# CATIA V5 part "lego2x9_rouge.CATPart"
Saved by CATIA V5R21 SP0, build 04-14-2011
Part number: lego2x9_rouge
Definition: Brique LEGO® 2x9, couleur Rouge
Description: Brique LEGO® 2x9, couleur Rouge
Property "SUPPLIER": "LEGO®"
Property "SUPPLIER": "LEGO®"
Property "DESIGN": "Brique LEGO® 2x9, couleur Rouge"
Property "DESIGN": "Brique LEGO® 2x9, couleur Rouge"
Property "TraceParts.PartNumber": "10-20122010-073060"
Property "TRACEPARTS": "TRACEPARTS"
Property "TraceParts.PartTitle": "Brique LEGO® 2x9"
Property "TraceParts.InstanceId": "10-20122010-07306010UFQ9W313DGN2O2A8ITDW7CR"
Property "TraceParts.PartVersion": "1.0.7"
Property "TraceParts.PartLanguage": "fr"
Bounding box of the stored display mesh (mm): x -4 to 68, y 0 to 11.2, z -4 to 12
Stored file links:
  C:\Users\2027.DESARCY-LEMIE30\Desktop\Legos\traité\lego2x9_rouge.CATPart
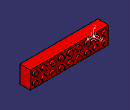
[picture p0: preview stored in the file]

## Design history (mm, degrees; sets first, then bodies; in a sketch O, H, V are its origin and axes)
AxisSystem1: origin (0, 0, 0), X (1, 0, 0), Y (0, 1, 0), Z (0, 0, 1)
Body1 "lego2x9_rouge" (main body)
  Solid1: solid without history
  Sketch1 on face of Solid1, origin (0, 0, 0), H (1, 0, 0), V (0, 0, 1)
    line L1 (-3, 11) -> (67, 11)
    line L2 (67, 11) -> (67, -3)
    line L3 (67, -3) -> (-3, -3)
    line L4 (-3, -3) -> (-3, 11)
    reference projected line E1 (-4, 12) -> (68, 12) from edge [face of Solid1 | face of Solid1]
    reference projected line E2 (-4, -4) -> (-4, 12) from edge [face of Solid1 | face of Solid1]
    reference projected line E3 (68, -4) -> (68, 12) from edge [face of Solid1 | face of Solid1]
    reference projected line E4 (-4, -4) -> (68, -4) from edge [face of Solid1 | face of Solid1]
    circle A1 centre (60, 4) radius 3
    circle A2 centre (44, 4) radius 3
    circle A3 centre (52, 4) radius 3
    reference projected circle E5 centre (60, 4) radius 2.4 from edge [face of Solid1 | face of Solid1]
    reference projected circle E6 centre (52, 4) radius 2.4 from edge [face of Solid1 | face of Solid1]
    reference projected circle E7 centre (44, 4) radius 2.4 from edge [face of Solid1 | face of Solid1]
    circle A4 centre (36, 4) radius 3
    point P8 (36, 4)
    reference projected circle E8 centre (36, 4) radius 2.4 from edge [face of Solid1 | face of Solid1]
    circle A5 centre (28, 4) radius 3
    point P9 (28, 4)
    point P10 (20, 4)
    circle A6 centre (20, 4) radius 3
    circle A7 centre (12, 4) radius 3
    circle A8 centre (4, 4) radius 3
    reference projected circle E9 centre (20, 4) radius 2.4 from edge [face of Solid1 | face of Solid1]
    reference projected circle E10 centre (28, 4) radius 2.4 from edge [face of Solid1 | face of Solid1]
    reference projected circle E11 centre (12, 4) radius 2.4 from edge [face of Solid1 | face of Solid1]
    reference projected circle E12 centre (4, 4) radius 2.4 from edge [face of Solid1 | face of Solid1]
    distance L1 E1 = 1
    distance E2 L4 = 1
    distance L2 E3 = 1
    distance L3 E4 = 1
    radius A1 = 3
    radius A3 = 3
    radius A2 = 3
    radius A4 = 3
    radius A5 = 3
    radius A6 = 3
    radius A7 = 3
    radius A8 = 3
    horizontal: L1 H, L3 H
    vertical: L2 V, L4 V
    concentricity: A1 E5, A3 E6, A2 E7, P8 E8, P10 E9, P9 E10, E11 A7, A8 E12
  Pocket1: profile Sketch1, direction (0, 1, 0), length 9
  Sketch2 on face of Solid1, origin (0, 1.6, 0), H (1, 0, 0), V (0, 0, 1)
    circle A1 centre (60, 4) radius 2.4
    point P1 (60, 4)
    circle A2 centre (52, 4) radius 2.4
    point P2 (52, 4)
    point P3 (44, 4)
    point P4 (36, 4)
    circle A3 centre (44, 4) radius 2.4
    circle A4 centre (36, 4) radius 2.4
    point P5 (28, 4)
    point P6 (20, 4)
    point P7 (12, 4)
    circle A5 centre (28, 4) radius 2.4
    circle A6 centre (20, 4) radius 2.4
    circle A7 centre (12, 4) radius 2.4
    circle A8 centre (4, 4) radius 2.4
    reference projected circle E1 centre (60, 4) radius 2.4 from edge [face of Solid1 | face of Solid1]
    reference projected circle E2 centre (60, 4) radius 2.4 from edge [face of Solid1 | face of Solid1]
    reference projected circle E3 centre (52, 4) radius 2.4 from edge [face of Solid1 | face of Solid1]
    reference projected circle E4 centre (52, 4) radius 2.4 from edge [face of Solid1 | face of Solid1]
    reference projected circle E5 centre (44, 4) radius 2.4 from edge [face of Solid1 | face of Solid1]
    reference projected circle E6 centre (44, 4) radius 2.4 from edge [face of Solid1 | face of Solid1]
    reference projected circle E7 centre (36, 4) radius 2.4 from edge [face of Solid1 | face of Solid1]
    reference projected circle E8 centre (36, 4) radius 2.4 from edge [face of Solid1 | face of Solid1]
    reference projected circle E9 centre (28, 4) radius 2.4 from edge [face of Solid1 | face of Solid1]
    reference projected circle E10 centre (28, 4) radius 2.4 from edge [face of Solid1 | face of Solid1]
    reference projected circle E11 centre (20, 4) radius 2.4 from edge [face of Solid1 | face of Solid1]
    reference projected circle E12 centre (20, 4) radius 2.4 from edge [face of Solid1 | face of Solid1]
    reference projected circle E13 centre (12, 4) radius 2.4 from edge [face of Solid1 | face of Solid1]
    reference projected circle E14 centre (12, 4) radius 2.4 from edge [face of Solid1 | face of Solid1]
    reference projected circle E15 centre (4, 4) radius 2.4 from edge [face of Solid1 | face of Solid1]
    reference projected circle E16 centre (4, 4) radius 2.4 from edge [face of Solid1 | face of Solid1]
    concentricity: P1 E1, P2 E3, P3 E5, P4 E7, P5 E9, P6 E11, P7 E13, E15 A8
    coincidence: A1 E2, E4 A2, A3 E6, E8 A4, A5 E10, E12 A6, A7 E14, E16 A8
  Pocket2: profile Sketch2, direction (0, 1, 0), length 7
